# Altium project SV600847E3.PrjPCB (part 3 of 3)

## Sheet SV600847E3_6_InterfaceControl.SchDoc
size 431 x 279 mm; Date: Not shown in title block; ApprovedBy: Not shown in title block; CheckedBy: Not shown in title block; Author: Not shown in title block; CompanyName: Not shown in title block; Engineer: Not shown in title block; Organization: Not shown in title block; Address1: Not shown in title block; Address2: Not shown in title block; Address3: Not shown in title block; Address4: Not shown in title block; DocumentNumber: 6; Revision: Use project parameter SCH_Rev; SheetNumber: 6; SheetTotal: 7; PageSetup: Record=PageOptions|CenterHorizontal=True|CenterVertical=True|PrintScale=1.00|XCorrection=1.00|YCorrection=1.00|PrintKind=0|BorderSize=5000000|LeftOffset=0|BottomOffset=0|Orientation=2|PaperLength=1000|PaperWidth=1000|Scale=100|PaperSource=15|PrintQuality=600|MediaType=1|DitherType=10|PaperKind=Letter|PrintScaleMode=1
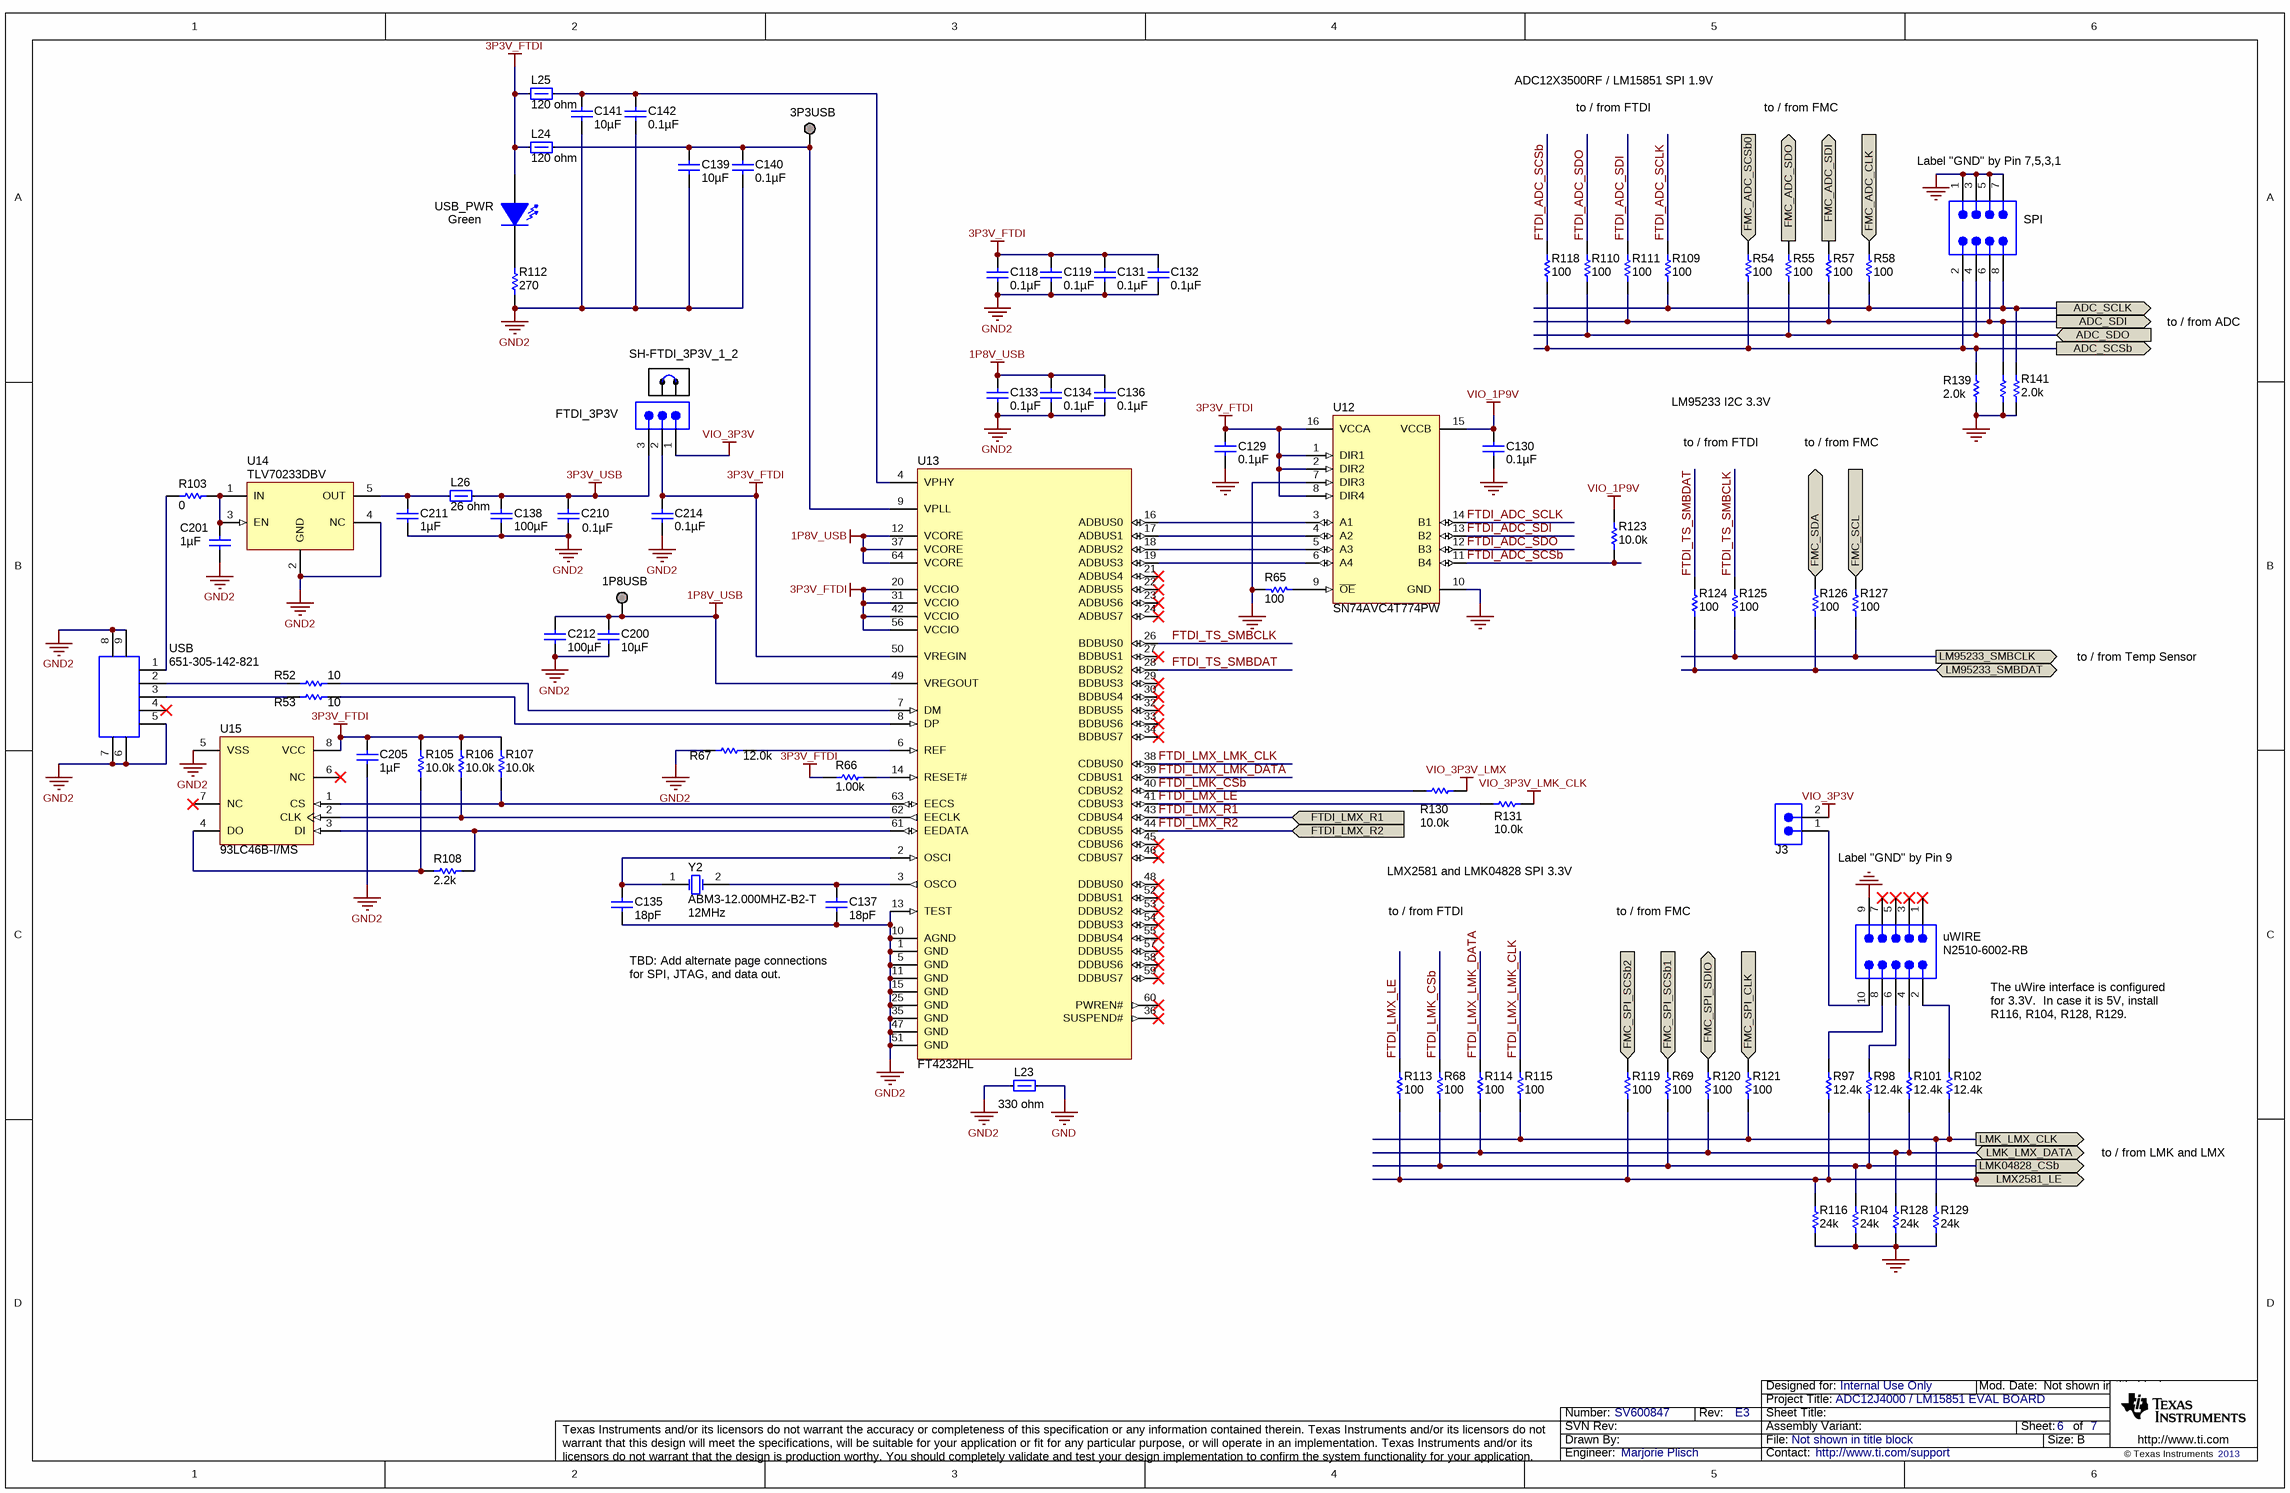
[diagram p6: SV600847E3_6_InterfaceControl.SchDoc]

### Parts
1P8USB  TESTPOINT  [TESTPOINT]  (value not drawn)  (no BOM)
3P3USB  TESTPOINT  [TESTPOINT]  (value not drawn)  (no BOM)
C118  ValueDisplayed: 0.1µF  [0201]  (hidden comment: C0603X5R0J104K)
C119  ValueDisplayed: 0.1µF  [0201]  (hidden comment: C0603X5R0J104K)
C129  ValueDisplayed: 0.1µF  [0603L]  (hidden comment: 06033C104JAT2A)
C130  ValueDisplayed: 0.1µF  [0603L]  (hidden comment: 06033C104JAT2A)
C131  ValueDisplayed: 0.1µF  [0201]  (hidden comment: C0603X5R0J104K)
C132  ValueDisplayed: 0.1µF  [0201]  (hidden comment: C0603X5R0J104K)
C133  ValueDisplayed: 0.1µF  [0201]  (hidden comment: C0603X5R0J104K)
C134  ValueDisplayed: 0.1µF  [0201]  (hidden comment: C0603X5R0J104K)
C135  ValueDisplayed: 18pF  [0402L]  (hidden comment: GRM1555C1H180JA01D)
C136  ValueDisplayed: 0.1µF  [0201]  (hidden comment: C0603X5R0J104K)
C137  ValueDisplayed: 18pF  [0402L]  (hidden comment: GRM1555C1H180JA01D)
C138  ValueDisplayed: 100µF  [1206L]  (hidden comment: GRM31CR60J107ME39L)
C139  ValueDisplayed: 10µF  [0603L]  (hidden comment: C1608X5R1A106M)
C140  ValueDisplayed: 0.1µF  [0201]  (hidden comment: C0603X5R0J104K)
C141  ValueDisplayed: 10µF  [0603L]  (hidden comment: C1608X5R1A106M)
C142  ValueDisplayed: 0.1µF  [0201]  (hidden comment: C0603X5R0J104K)
C200  ValueDisplayed: 10µF  [0603L]  (hidden comment: C1608X5R1A106M)
C201  ValueDisplayed: 1µF  [0603L]  (hidden comment: C1608X5R1C105K)
C205  ValueDisplayed: 1µF  [0603L]  (hidden comment: C1608X5R1A105K)
C210  ValueDisplayed: 0.1µF  [0603L]  (hidden comment: 0603YC104JAT2A)
C211  ValueDisplayed: 1µF  [0603L]  (hidden comment: C1608X5R1C105K)
C212  ValueDisplayed: 100µF  [1206]  (hidden comment: GRM31CR60J107ME39L)
C214  ValueDisplayed: 0.1µF  [0201]  (hidden comment: C0603X5R0J104K)
FTDI_3P3V  TSW-103-07-G-S  [TSW-103-07-G-S]  (value not drawn)
J3  TSW-102-07-G-S  [TSW-102-07-G-S]  (value not drawn)
L23  value 330 ohm  [0603]  (hidden comment: BLM18SG331TN1D)
L24  value 120 ohm  [0603]  (hidden comment: BLM18SG121TN1D)
L25  value 120 ohm  [0603L]  (hidden comment: BLM18SG121TN1D)
L26  value 26 ohm  [0603]  (hidden comment: BLM18SG260TN1D)
R52  value 10  [0603L]  (hidden comment: CRCW060310R0JNEA)
R53  value 10  [0603L]  (hidden comment: CRCW060310R0JNEA)
R54  value 100  [0603L]  (hidden comment: CRCW0603100RJNEA)
R55  value 100  [0603L]  (hidden comment: CRCW0603100RJNEA)
R57  value 100  [0603L]  (hidden comment: CRCW0603100RJNEA)
R58  value 100  [0603L]  (hidden comment: CRCW0603100RJNEA)
R65  value 100  [0603L]  (hidden comment: CRCW0603100RJNEA)
R66  value 1.00k  [0603L]  (hidden comment: CRCW06031K00FKEA)
R67  value 12.0k  [0603L]  (hidden comment: RC0603FR-0712KL)
R68  value 100  [0603L]  (hidden comment: CRCW0603100RJNEA)
R69  value 100  [0603L]  (hidden comment: CRCW0603100RJNEA)
R97  value 12.4k  [0603L]  (hidden comment: CRCW060312K4FKEA)
R98  value 12.4k  [0603L]  (hidden comment: CRCW060312K4FKEA)
R101  value 12.4k  [0603L]  (hidden comment: CRCW060312K4FKEA)
R102  value 12.4k  [0603L]  (hidden comment: CRCW060312K4FKEA)
R103  value 0  [0603L]  (hidden comment: CRCW06030000Z0EA)
R104  value 24k  [0402L]  (hidden comment: CRCW040224K0JNED)
R105  value 10.0k  [0603L]  (hidden comment: CRCW060310K0FKEA)
R106  value 10.0k  [0603L]  (hidden comment: CRCW060310K0FKEA)
R107  value 10.0k  [0603L]  (hidden comment: CRCW060310K0FKEA)
R108  value 2.2k  [0603L]  (hidden comment: RC0603JR-072K2L)
R109  value 100  [0603L]  (hidden comment: CRCW0603100RJNEA)
R110  value 100  [0603L]  (hidden comment: CRCW0603100RJNEA)
R111  value 100  [0603L]  (hidden comment: CRCW0603100RJNEA)
R112  value 270  [0603L]  (hidden comment: CRCW0603270RJNEA)
R113  value 100  [0603L]  (hidden comment: CRCW0603100RJNEA)
R114  value 100  [0603L]  (hidden comment: CRCW0603100RJNEA)
R115  value 100  [0603L]  (hidden comment: CRCW0603100RJNEA)
R116  value 24k  [0402L]  (hidden comment: CRCW040224K0JNED)
R118  value 100  [0603L]  (hidden comment: CRCW0603100RJNEA)
R119  value 100  [0603L]  (hidden comment: CRCW0603100RJNEA)
R120  value 100  [0603L]  (hidden comment: CRCW0603100RJNEA)
R121  value 100  [0603L]  (hidden comment: CRCW0603100RJNEA)
R123  value 10.0k  [0603L]  (hidden comment: CRCW060310K0FKEA)
R124  value 100  [0603L]  (hidden comment: CRCW0603100RJNEA)
R125  value 100  [0603L]  (hidden comment: CRCW0603100RJNEA)
R126  value 100  [0603L]  (hidden comment: CRCW0603100RJNEA)
R127  value 100  [0603L]  (hidden comment: CRCW0603100RJNEA)
R128  value 24k  [0402L]  (hidden comment: CRCW040224K0JNED)
R129  value 24k  [0402L]  (hidden comment: CRCW040224K0JNED)
R130  value 10.0k  [0603L]  (hidden comment: CRCW060310K0FKEA)
R131  value 10.0k  [0603L]  (hidden comment: CRCW060310K0FKEA)
R139  value 2.0k  [0603L]  (hidden comment: CRCW06032K00JNEA)
R140  CRCW06032K00JNEA  [0603L]  (value not drawn)
R141  value 2.0k  [0603L]  (hidden comment: CRCW06032K00JNEA)
SH-FTDI_3P3V_1_2  SNT-100-BK-G  [SNT-100-BK-G]  (value not drawn)
SPI  TSW-104-07-G-D  [TSW-104-07-G-D]  (value not drawn)
U12  SN74AVC4T774PW  [PW0016A_L]
U13  FT4232HL  [LQFP64_N]
U14  TLV70233DBV  [DBV0005A_N]
U15  93LC46B-I/MS  [MSOP-MS8_N]
USB  651-305-142-821  [CONN_USB-MINI-AB-651-305-142-821]
USB_PWR  value Green  [LED_LTST-C190]  (hidden comment: LTST-C190GKT)
uWIRE  N2510-6002-RB  [CONN_2510-6002]
Y2  ABM3-12.000MHZ-B2-T  Frequency: 12MHz  [XTAL_ABM3]

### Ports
ADC_SCLK (out), ADC_SCSb (out), ADC_SDI (out), ADC_SDO (in), FMC_ADC_CLK (in), FMC_ADC_SCSb0 (in), FMC_ADC_SDI (out), FMC_ADC_SDO (in), FMC_SCL (out), FMC_SDA (bidir), FMC_SPI_CLK (in), FMC_SPI_SCSb1 (in), FMC_SPI_SCSb2 (in), FMC_SPI_SDIO (bidir), FTDI_LMX_R1, FTDI_LMX_R2, LM95233_SMBCLK (out), LM95233_SMBDAT (bidir), LMK04828_CSb (out), LMK_LMX_CLK, LMK_LMX_DATA (bidir), LMX2581_LE (out)

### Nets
1P8V_USB: 1P8USB.1 C133.1 C134.1 C136.1 C200.1 C212.2 U13.12(VCORE) U13.37(VCORE) U13.49(VREGOUT) U13.64(VCORE)
3P3V_FTDI: C118.1 C119.1 C129.1 C131.1 C132.1 C205.1 C214.1 FTDI_3P3V.2 L24.1 L25.1 R66.2 R105.2 R106.2 R107.2 U12.1(DIR1) U12.2(DIR2) U12.8(DIR4) U12.16(VCCA) U13.20(VCCIO) U13.31(VCCIO) U13.42(VCCIO) U13.50(VREGIN) U13.56(VCCIO) U15.8(VCC) USB_PWR.1(A)
3P3V_USB: C138.1 C210.1 FTDI_3P3V.3 L26.2
GND: C129.2 C130.2 L23.2 R65.1 R104.1 R116.1 R128.1 R129.1 R139.1 R140.1 R141.1 SPI.1 SPI.3 SPI.5 SPI.7 U12.7(DIR3) U12.10(GND) uWIRE.9
GND2: C118.2 C119.2 C131.2 C132.2 C133.2 C134.2 C135.2 C136.2 C137.2 C138.2 C139.2 C140.2 C141.2 C142.2 C200.2 C201.2 C205.2 C210.2 C211.2 C212.1 C214.2 L23.1 R67.1 R112.1 U13.1(GND) U13.5(GND) U13.10(AGND) U13.11(GND) U13.13(TEST) U13.15(GND) U13.25(GND) U13.35(GND) U13.47(GND) U13.51(GND) U14.2(GND) U14.4(NC) U15.5(VSS) USB.5 USB.6 USB.7 USB.8 USB.9
VIO_1P9V: C130.1 R123.2 U12.15(VCCB)
VIO_3P3V: FTDI_3P3V.1 J3.2
VIO_3P3V_LMK_CLK: R131.1
VIO_3P3V_LMX: R130.1
FTDI_ADC_SCLK: R109.2 U12.14(B1)
FTDI_ADC_SCSb: R118.2 R123.1 U12.11(B4)
FTDI_ADC_SDI: R111.2 U12.13(B2)
FTDI_ADC_SDO: R110.2 U12.12(B3)
FTDI_LMK_CSb: R68.2 R130.2 U13.40(CDBUS2)
FTDI_LMX_LE: R113.2 R131.2 U13.41(CDBUS3)
FTDI_LMX_LMK_CLK: R115.2 U13.38(CDBUS0)
FTDI_LMX_LMK_DATA: R114.2 U13.39(CDBUS1)
FTDI_LMX_R1: U13.43(CDBUS4) ; port FTDI_LMX_R1
FTDI_LMX_R2: U13.44(CDBUS5) ; port FTDI_LMX_R2
FTDI_TS_SMBCLK: R125.2 U13.26(BDBUS0)
FTDI_TS_SMBDAT: R124.2 U13.28(BDBUS2)
LMK04828_CSb: R68.1 R69.1 R98.1 R104.2 ; port LMK04828_CSb
LMK_LMX_CLK: R102.1 R115.1 R121.1 R129.2 ; port LMK_LMX_CLK
LMK_LMX_DATA: R101.1 R114.1 R120.1 R128.2 ; port LMK_LMX_DATA
LMX2581_LE: R97.1 R113.1 R116.2 R119.1 ; port LMX2581_LE
Net3P3USB_1: 3P3USB.1 C139.1 C140.1 L24.2 U13.9(VPLL)
NetC135_1: C135.1 U13.2(OSCI) Y2.1(OSC1)
NetC137_1: C137.1 U13.3(OSCO) Y2.2(OSC2)
NetC141_1: C141.1 C142.1 L25.2 U13.4(VPHY)
NetC201_1: C201.1 R103.2 U14.1(IN) U14.3(EN)
NetC211_1: C211.1 L26.1 U14.5(OUT)
NetFMC_RX1_C30: R127.2 ; port FMC_SCL
NetFMC_RX1_C31: R126.2 ; port FMC_SDA
NetFMC_RX1_G30: R121.2 ; port FMC_SPI_CLK
NetFMC_RX1_G33: R69.2 ; port FMC_SPI_SCSb1
NetFMC_RX1_G34: R119.2 ; port FMC_SPI_SCSb2
NetFMC_RX1_G36: R57.2 ; port FMC_ADC_SDI
NetFMC_RX1_G37: R55.2 ; port FMC_ADC_SDO
NetFMC_RX1_H34: R120.2 ; port FMC_SPI_SDIO
NetFMC_RX1_H37: R58.2 ; port FMC_ADC_CLK
NetFMC_RX1_H38: R54.2 ; port FMC_ADC_SCSb0
NetJ3_1: J3.1 uWIRE.10
NetR31_1: R124.1 R126.1 ; port LM95233_SMBDAT
NetR32_1: R125.1 R127.1 ; port LM95233_SMBCLK
NetR52_1: R52.1 USB.2
NetR52_2: R52.2 U13.7(DM)
NetR53_1: R53.1 USB.3
NetR53_2: R53.2 U13.8(DP)
NetR54_1: R54.1 R118.1 R139.2 SPI.2 ; port ADC_SCSb
NetR55_1: R55.1 R110.1 SPI.4 ; port ADC_SDO
NetR57_1: R57.1 R111.1 R140.2 SPI.6 ; port ADC_SDI
NetR58_1: R58.1 R109.1 R141.2 SPI.8 ; port ADC_SCLK
NetR65_2: R65.2 U12.9(~{OE})
NetR66_1: R66.1 U13.14(RESET#)
NetR67_2: R67.2 U13.6(REF)
NetR97_2: R97.2 uWIRE.8
NetR98_2: R98.2 uWIRE.6
NetR101_2: R101.2 uWIRE.4
NetR102_2: R102.2 uWIRE.2
NetR103_1: R103.1 USB.1
NetR105_1: R105.1 R108.2 U15.4(DO)
NetR106_1: R106.1 U13.62(EECLK) U15.2(CLK)
NetR107_1: R107.1 U13.63(EECS) U15.1(CS)
NetR108_1: R108.1 U13.61(EEDATA) U15.3(DI)
NetR112_2: R112.2 USB_PWR.2(K)
NetU12_3: U12.3(A1) U13.16(ADBUS0)
NetU12_4: U12.4(A2) U13.17(ADBUS1)
NetU12_5: U12.5(A3) U13.18(ADBUS2)
NetU12_6: U12.6(A4) U13.19(ADBUS3)

Not connected (* = marked no-connect by the designer): U13 21(ADBUS4)* 22(ADBUS5)* 23(ADBUS6)* 24(ADBUS7)* 27(BDBUS1)* 29(BDBUS3)* 30(BDBUS4)* 32(BDBUS5)* 33(BDBUS6)* 34(BDBUS7)* 36(SUSPEND#)* 45(CDBUS6)* 46(CDBUS7)* 48(DDBUS0)* 52(DDBUS1)* 53(DDBUS2)* 54(DDBUS3)* 55(DDBUS4)* 57(DDBUS5)* 58(DDBUS6)* 59(DDBUS7)* 60(PWREN#)*; U15 6(NC)* 7(NC)*; USB 4*; uWIRE 1* 3* 5* 7*

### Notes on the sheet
- ADC12X3500RF / LM15851 SPI 1.9V
- to / from FTDI
- to / from FMC
- (near SPI) Label "GND" by Pin 7,5,3,1
- to / from ADC
- LM95233 I2C 3.3V
- to / from Temp Sensor
- LMX2581 and LMK04828 SPI 3.3V
- Label "GND" by Pin 9
- TBD: Add alternate page connections for SPI, JTAG, and data out.
- The uWire interface is configured for 3.3V.  In case it is 5V, install R116, R104, R128, R129.
- to / from LMK and LMX

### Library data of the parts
1P8USB 3P3USB = TESTPOINT: TEST POINT.  No entry in BOM.
C118 C119 C131-C134 C136 C140 C142 C214 = Capacitor: CAP, CERM, 0.1uF, 6.3V, X5R, 10%, 0201; Manufacturer: TDK; Polarized: N; U/M: EA
C129 C130 = 06033C104JAT2A: CAP, CERM, 0.1uF, 25V, +/-5%, X7R, 0603; Manufacturer: AVX; Polarized: N; CompType: Capacitor; U/M: EA; Cap_F: 0.0000001; Tolerance_%: 5; ESR_Ohm: 0.05; Value1: 0.05 ohm; VDC_V: 25; TaMin_C: -55; TaMax_C: 125; Cap_Case: 0603
C135 C137 = GRM1555C1H180JA01D: CAP, CERM, 18pF, 50V, +/-5%, C0G/NP0, 0402; Manufacturer: MuRata; Polarized: N; CompType: Capacitor; U/M: EA; Cap_F: 0.000000000018; Tolerance_%: 5; Value1: Unknown; VDC_V: 50; TaMin_C: -55; TaMax_C: 125; Cap_Case: 0402
C138 = GRM31CR60J107ME39L: CAP, CERM, 100uF, 6.3V, +/-20%, X5R, 1206; Manufacturer: MuRata; Polarized: N; CompType: Capacitor; U/M: EA; Cap_F: 0.0001; Tolerance_%: 20; ESR_Ohm: 0.003; Value1: 0.003 ohm; VDC_V: 6.3; TaMin_C: -55; TaMax_C: 85; Cap_Case: 1206
C139 C141 C200 = C1608X5R1A106M: CAP, CERM, 10uF, 10V, +/-10%, C0G/NP0, 0603; Manufacturer: TDK; Polarized: N; CompType: Capacitor; U/M: EA; Cap_F: 0.00001; Tolerance_%: 10; ESR_Ohm: 0.0078; Value1: 0.0078 ohm; IRMS_A: 1.85; TaMin_C: -55; TaMax_C: 85; Cap_Case: 0603
C201 C211 = C1608X5R1C105K: CAP, CERM, 1uF, 16V, +/-10%, X5R, 0603; Manufacturer: TDK; Polarized: N; CompType: Capacitor; U/M: EA; Cap_F: 0.000001; Tolerance_%: 10; ESR_Ohm: 0.0057; Value1: 0.0057 ohm; VDC_V: 16; TaMin_C: -55; TaMax_C: 85; Cap_Case: 0603
C205 = C1608X5R1A105K: CAP, CERM, 1uF, 10V, +/-10%, X5R, 0603; Manufacturer: TDK; Polarized: N; CompType: Capacitor; U/M: EA; Cap_F: 0.000001; Tolerance_%: 10; ESR_Ohm: 0.0057; Value1: 0.0057 ohm; TaMin_C: -55; TaMax_C: 85; Cap_Case: 0603
C210 = 0603YC104JAT2A: CAP, CERM, 0.1uF, 16V, +/-5%, X7R, 0603; Manufacturer: AVX; Polarized: N; CompType: Capacitor; U/M: EA; Cap_F: 0.0000001; Tolerance_%: 5; ESR_Ohm: 0.039; Value1: 0.039 ohm; VDC_V: 16; TaMin_C: -55; TaMax_C: 125; Cap_Case: 0603
C212 = GRM31CR60J107ME39L: CAP, CERM, 100uF, 6.3V, +/-20%, X5R, 1206; Manufacturer: MuRata; Polarized: N; CompType: Capacitor; U/M: EA; Cap_F: 0.0001; Tolerance_%: 20; ESR_Ohm: 0.003; Value1: 0.003 ohm; VDC_V: 6.3; TaMin_C: -55; TaMax_C: 85
FTDI_3P3V = TSW-103-07-G-S: Header, TH, 100mil, 3x1, Gold plated, 230 mil above insulator; Manufacturer: Samtec, Inc.; Alternate Manufacturer: Any; Alternate PartNumber: Equivalent; U/M: EA
J3 = TSW-102-07-G-S: Header, TH, 100mil, 2x1, Gold plated, 230 mil above insulator; Manufacturer: Samtec, Inc.; U/M: EA
L23 = BLM18SG331TN1D: 1.5A Ferrite Bead, 330 ohm @ 100MHz, SMD; Manufacturer: MuRata; Imax_A: 1.5; DCR_ohm: 0.07; Value1: 0.07 ohm; ZTyp@100MHz_Ohm: 330; U/M: EA
L24 L25 = BLM18SG121TN1D: 3A Ferrite Bead, 120 ohm @ 100MHz, SMD; Manufacturer: MuRata; Imax_A: 3; DCR_ohm: 0.025; Value1: 0.025 ohm; ZTyp@100MHz_Ohm: 120; U/M: EA
L26 = BLM18SG260TN1D: 6A Ferrite Bead, 26 ohm @ 100MHz, SMD; Manufacturer: MuRata; Imax_A: 6; DCR_ohm: 0.007; Value1: 0.007 ohm; ZTyp@100MHz_Ohm: 26; U/M: EA
R52 R53 = CRCW060310R0JNEA: RES, 10 ohm, 5%, 0.1W, 0603; Manufacturer: Vishay-Dale; CompType: Resistor; Value_Code: 10R0; Tolerance_%: 5; Power_W: 0.1; VDC_V: 75; TempCo: 200 ppm/C; EIA_Code: E24; U/M: EA
R54 R55 R57 R58 R65 R68 R69 R109-R111 R113-R115 R118-R121 R124-R127 = CRCW0603100RJNEA: RES, 100 ohm, 5%, 0.1W, 0603; Manufacturer: Vishay-Dale; CompType: Resistor; Value_Code: 100R; Tolerance_%: 5; Power_W: 0.1; VDC_V: 75; TempCo: 200 ppm/C; EIA_Code: E24; U/M: EA
R66 = CRCW06031K00FKEA: RES, 1.00k ohm, 1%, 0.1W, 0603; Manufacturer: Vishay-Dale; CompType: Resistor; Tolerance_%: 1; VDC_V: 75; Power_W: 0.1; Res_ohm: 1000; TempCo_ppm/C: 100; Value_Code: 1k00; EIA_Code: E96; U/M: EA
R67 = RC0603FR-0712KL: RES, 12.0k ohm, 1%, 0.1W, 0603; Manufacturer: Yageo America; CompType: Resistor; Res_ohm: 12000; Value_Code: 12k0; Tolerance_%: 1; Power_W: 0.1; VDC_V: 150; TempCo: 200 ppm/C; U/M: EA
R97 R98 R101 R102 = CRCW060312K4FKEA: RES, 12.4k ohm, 1%, 0.1W, 0603; Manufacturer: Vishay-Dale; CompType: Resistor; Res_ohm: 12400; Value_Code: 12k4; Tolerance_%: 1; Power_W: 0.1; VDC_V: 75; TempCo: 100 ppm/C; EIA_Code: E96; U/M: EA
R103 = CRCW06030000Z0EA: RES, 0 ohm, 5%, 0.1W, 0603; Manufacturer: Vishay-Dale; CompType: Resistor; Value_Code: 0000; Tolerance_%: 5; Power_W: 0.1; VDC_V: 75; TempCo: 200 ppm/C; EIA_Code: E24; U/M: EA
R104 R116 R128 R129 = CRCW040224K0JNED: RES, 24k ohm, 5%, 0.063W, 0402; Manufacturer: Vishay-Dale; CompType: Resistor; Res_ohm: 24000; Value_Code: 24k0; Tolerance_%: 5; Power_W: 0.063; VDC_V: 50; TempCo: 200 ppm/C; EIA_Code: E24; U/M: EA
R105-R107 R123 R130 R131 = CRCW060310K0FKEA: RES, 10.0k ohm, 1%, 0.1W, 0603; Manufacturer: Vishay-Dale; CompType: Resistor; Res_ohm: 10000; Value_Code: 10k0; Tolerance_%: 1; Power_W: 0.1; VDC_V: 75; TempCo: 100 ppm/C; EIA_Code: E96; U/M: EA
R108 = RC0603JR-072K2L: RES, 2.2k ohm, 5%, 0.1W, 0603; Manufacturer: Yageo America; CompType: Resistor; Res_ohm: 2200; Value_Code: 2k20; Tolerance_%: 5; Power_W: 0.1; VDC_V: 50; TempCo: 100 ppm/C; EIA_Code: E24; U/M: EA
R112 = CRCW0603270RJNEA: RES, 270 ohm, 5%, 0.1W, 0603; Manufacturer: Vishay-Dale; Alternate Manufacturer: Any; Alternate PartNumber: Equivalent; CompType: Resistor; Value_Code: 270R; Tolerance_%: 5; Power_W: 0.1; VDC_V: 75; TempCo: 200 ppm/C; EIA_Code: E24; U/M: EA
R139-R141 = CRCW06032K00JNEA: RES, 2.0k ohm, 5%, 0.1W, 0603; Manufacturer: Vishay-Dale; CompType: Resistor; Res_ohm: 2000; Value_Code: 2k00; Tolerance_%: 5; Power_W: 0.1; VDC_V: 75; TempCo: 200 ppm/C; EIA_Code: E24; U/M: EA
SH-FTDI_3P3V_1_2 = SNT-100-BK-G: Shunt, 100mil, Gold plated, Black; Manufacturer: Samtec, Inc.; Alternate Manufacturer: 3M; Alternate PartNumber: 969102-0000-DA; Value: 1x2; Note: You can "mate" this to a header by matching the designator.  i.e. use SH-J3 for header J3
SPI = TSW-104-07-G-D: Header, TH, 100mil, 4x2, Gold plated, 230 mil above insulator; Manufacturer: Samtec, Inc.; U/M: EA
U12 = SN74AVC4T774PW: 4-BIT DUAL-SUPPLY BUS TRANSCEIVER WITH CONFIGURABLE VOLTAGE TRANSLATION AND 3-STATE OUTPUTS, PW0016A; Alternate Manufacturer: None; Manufacturer: Texas Instruments; SymbolCreator: a0411947; CompType: IC; U/M: EA
U13 = FT4232HL: Quad High Speed USB to Multipurpose UART/MPSSE IC; Manufacturer: FTDI; SymbolCreator: a0411947
U14 = TLV70233DBV: 300-mA, Low-IQ, Low-Dropout Regulator, DBV0005A; Alternate Manufacturer: None; Manufacturer: Texas Instruments; SymbolCreator: a0411947; CompType: IC; U/M: EA
U15 = 93LC46B-I/MS: 1K, 64x16-bit, 2.5V Microwire Serial EEPROM, 8-Pin MSOP, Industrial Temperature
USB = 651-305-142-821: MINI USB 2.0 SMT TYPE AB 5 CONTACTS R/A, SMD; Manufacturer: Wurth Elektronik eiSos; SymbolCreator: a0799628; CompType: Connector; U/M: EA
USB_PWR = LTST-C190GKT: LED, Green, SMD; Manufacturer: Lite-On; Vf_V: 2.1; Value2: 2.1V; Io_A: 0.02; Power_TotalModule: 0.1; Value1: 0.1W; U/M: EA
uWIRE = N2510-6002-RB: Connector, 100mil Shrouded, 5x2, High-Temperature, Gold, TH; Manufacturer: 3M; SymbolCreator: a0412235; U/M: EA
Y2 = ABM3-12.000MHZ-B2-T: Crystal, 12Mhz, 18pF, SMD; Manufacturer: Abracon Corportation; SymbolCreator: a0412235; U/M: EA; TaMin_C: -20; TaMax_C: 70; Frequency Stability: ±50ppm

## Sheet SV600847E3_7_Hardware.SchDoc
size 431 x 279 mm; Date: Not shown in title block; ApprovedBy: Not shown in title block; CheckedBy: Not shown in title block; Author: Not shown in title block; CompanyName: Not shown in title block; Engineer: Not shown in title block; Organization: Not shown in title block; Address1: Not shown in title block; Address2: Not shown in title block; Address3: Not shown in title block; Address4: Not shown in title block; DocumentNumber: 7; Revision: Use project parameter SCH_Rev; SheetNumber: 7; SheetTotal: 7; PageSetup: Record=PageOptions|CenterHorizontal=True|CenterVertical=True|PrintScale=1.00|XCorrection=1.00|YCorrection=1.00|PrintKind=0|BorderSize=5000000|LeftOffset=0|BottomOffset=0|Orientation=2|PaperLength=1000|PaperWidth=1000|Scale=100|PaperSource=15|PrintQuality=600|MediaType=1|DitherType=10|PaperKind=Letter|PrintScaleMode=1
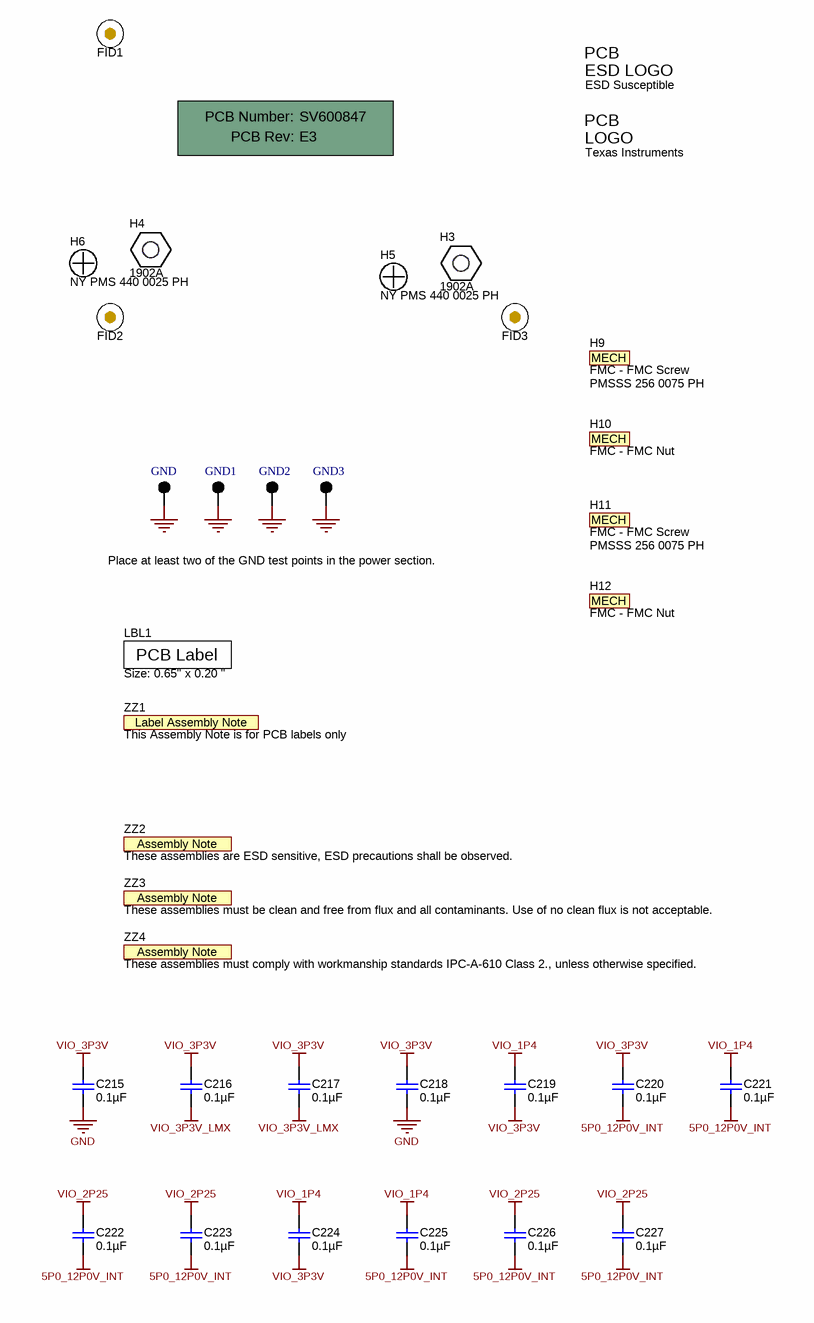
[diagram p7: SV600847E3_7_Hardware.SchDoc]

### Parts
!PCB  Printed Circuit Board  (value not drawn)  (mechanical)
C215  ValueDisplayed: 0.1µF  [0402L]  (hidden comment: GRM155R71A104KA01D)
C216  ValueDisplayed: 0.1µF  [0402L]  (hidden comment: GRM155R71A104KA01D)
C217  ValueDisplayed: 0.1µF  [0402L]  (hidden comment: GRM155R71A104KA01D)
C218  ValueDisplayed: 0.1µF  [0402L]  (hidden comment: GRM155R71A104KA01D)
C219  ValueDisplayed: 0.1µF  [0402L]  (hidden comment: GRM155R71A104KA01D)
C220  ValueDisplayed: 0.1µF  [0402L]  (hidden comment: GRM155R71A104KA01D)
C221  ValueDisplayed: 0.1µF  [0402L]  (hidden comment: GRM155R71A104KA01D)
C222  ValueDisplayed: 0.1µF  [0402L]  (hidden comment: GRM155R71A104KA01D)
C223  ValueDisplayed: 0.1µF  [0402L]  (hidden comment: GRM155R71A104KA01D)
C224  ValueDisplayed: 0.1µF  [0402L]  (hidden comment: GRM155R71A104KA01D)
C225  ValueDisplayed: 0.1µF  [0402L]  (hidden comment: GRM155R71A104KA01D)
C226  ValueDisplayed: 0.1µF  [0402L]  (hidden comment: GRM155R71A104KA01D)
C227  ValueDisplayed: 0.1µF  [0402L]  (hidden comment: GRM155R71A104KA01D)
FID1  Fiducial  [Fiducial10-30]  (value not drawn)
FID2  Fiducial  [Fiducial10-30]  (value not drawn)
FID3  Fiducial  [Fiducial10-30]  (value not drawn)
GND  5011  [Keystone5011]  (value not drawn)
GND1  5011  [Keystone5011]  (value not drawn)
GND2  5011  [Keystone5011]  (value not drawn)
GND3  5011  [Keystone5011]  (value not drawn)
H3  1902A  [Keystone_1902C]
H4  1902A  [Keystone_1902C]
H5  NY PMS 440 0025 PH  [NY PMS 440 0025 PH]
H6  NY PMS 440 0025 PH  [NY PMS 440 0025 PH]
H9  FMC - FMC Screw  PartNumber: PMSSS 256 0075 PH  (mechanical)
H10  FMC - FMC Nut  (mechanical)
H11  FMC - FMC Screw  PartNumber: PMSSS 256 0075 PH  (mechanical)
H12  FMC - FMC Nut  (mechanical)
LBL1  Size: 0.65" x 0.20 "  [Label_650x200]
Logo1  ESD Susceptible  [ESD_Overlay_Small]  (no BOM)
Logo2  Texas Instruments  [TI_Symbol_Overlay_Small]  (no BOM)
ZZ1  This Assembly Note is for PCB labels only  [AssemblyNoteLabel]  (no BOM)
ZZ2  These assemblies are ESD sensitive, ESD precautions shall be observed.  [AssemblyNote]  (no BOM)
ZZ3  These assemblies must be clean and free from flux and all contaminants. Use of no clean flux is not acceptable.  [AssemblyNote]  (no BOM)
ZZ4  These assemblies must comply with workmanship standards IPC-A-610 Class 2., unless otherwise specified.  [AssemblyNote]  (no BOM)

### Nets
5P0_12P0V_INT: C220.2 C221.2 C222.2 C223.2 C225.2 C226.2 C227.2
GND: C215.2 C218.2 GND.1 GND1.1 GND2.1 GND3.1
VIO_1P4: C219.1 C221.1 C224.1 C225.1
VIO_2P25: C222.1 C223.1 C226.1 C227.1
VIO_3P3V: C215.1 C216.1 C217.1 C218.1 C219.2 C220.1 C224.2
VIO_3P3V_LMX: C216.2 C217.2

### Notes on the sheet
- Place at least two of the GND test points in the power section.

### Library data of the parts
!PCB = PCB: Manufacturer: Any; PartNumber: SV600847; SymbolCreator: a0412235
C215-C227 = GRM155R71A104KA01D: CAP, CERM, 0.1uF, 10V, +/-10%, X7R, 0402; Manufacturer: MuRata; Polarized: N; CompType: Capacitor; U/M: EA; Cap_F: 0.0000001; Tolerance_%: 10; TaMin_C: -55; TaMax_C: 125; Cap_Case: 0402
FID1-FID3 = Fiducial: Fiducial mark.  There is nothing to buy or mount.; SymbolCreator: codlsc
GND GND1-GND3 = 5011: Test Point, TH, Multipurpose, Black; Manufacturer: Keystone Electronics; CompType: Test Point Loop
H3 H4 = 1902C: Standoff, Hex, 0.25"L #4-40 Nylon; Manufacturer: Keystone; CompType: Hardware; U/M: EA
H5 H6 = NY PMS 440 0025 PH: Machine Screw, Round, #4-40 x 1/4, Nylon, Philips panhead; Manufacturer: B&F Fastener Supply; CompType: Hardware; SymbolCreator: codlsc; U/M: EA
H9 H11 = MechPart: Will add component to BOM.  Useful for cables, nuts, etc. not in libraries; Manufacturer: B&F Fastner Supply; SymbolCreator: codlsc; CompType: Mechanical; U/M: EA
H10 H12 = MechPart: Will add component to BOM.  Useful for cables, nuts, etc. not in libraries; Manufacturer: B & F Fastener Supply; PartNumber: HNSS256; SymbolCreator: codlsc; CompType: Mechanical; U/M: EA
LBL1 = THT-14-423-10: Thermal Transfer Printable Labels, 0.650" W x 0.200" H - 10,000 per roll; Manufacturer: Brady; SymbolCreator: a0412235; CompType: Label
Logo1 = ESD_Susceptible: ESD Susceptible Symbol; SymbolCreator: codlsc
Logo2 = TI_Logo: Texas Instrument Corporate Signature; SymbolCreator: codlsc
ZZ1 = AssemblyNoteLabel: SymbolCreator: a0412235
ZZ2-ZZ4 = AssemblyNote: SymbolCreator: codlsc

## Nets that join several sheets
5P0_12P0V_INT: SV600847E3_5_Power (16 pins), SV600847E3_7_Hardware (7 pins)
12P0V_RX: SV600847E3_2_FMC (FMC_RX1.C35 FMC_RX1.C37), SV600847E3_5_Power (EXT5V_FMC12V.3)
GND: SV600847E3_1_ADC_IO (101 pins), SV600847E3_2_FMC (164 pins), SV600847E3_3_LMX2581 (33 pins), SV600847E3_4_LMK04828 (31 pins), SV600847E3_5_Power (80 pins), SV600847E3_6_InterfaceControl (18 pins), SV600847E3_7_Hardware (6 pins)
VIO_1P2VA: SV600847E3_1_ADC_IO (18 pins), SV600847E3_5_Power (C177.1 C188.1 L15.2)
VIO_1P2VD: SV600847E3_1_ADC_IO (28 pins), SV600847E3_5_Power (C189.1 C197.1 L16.2)
VIO_1P4: SV600847E3_5_Power (5 pins), SV600847E3_7_Hardware (C219.1 C221.1 C224.1 C225.1)
VIO_1P9V: SV600847E3_1_ADC_IO (20 pins), SV600847E3_5_Power (6 pins), SV600847E3_6_InterfaceControl (C130.1 R123.2 U12.15)
VIO_2P25: SV600847E3_5_Power (5 pins), SV600847E3_7_Hardware (C222.1 C223.1 C226.1 C227.1)
VIO_3P3V: SV600847E3_1_ADC_IO (15 pins), SV600847E3_5_Power (C153.1 C163.1 L9.2), SV600847E3_6_InterfaceControl (FTDI_3P3V.1 J3.2), SV600847E3_7_Hardware (7 pins)
VIO_3P3V_LMK_CLK: SV600847E3_4_LMK04828 (6 pins), SV600847E3_5_Power (C116.1 C171.1 L13.2), SV600847E3_6_InterfaceControl (R131.1)
VIO_3P3V_LMK_PLL: SV600847E3_4_LMK04828 (16 pins), SV600847E3_5_Power (C164.1 C165.1 L10.2)
VIO_3P3V_LMX: SV600847E3_3_LMX2581 (25 pins), SV600847E3_5_Power (C144.1 C152.1 L6.2), SV600847E3_6_InterfaceControl (R130.1), SV600847E3_7_Hardware (C216.2 C217.2)
D0_N: SV600847E3_1_ADC_IO (C9.1), SV600847E3_2_FMC (FMC_RX1.C6)
D0_P: SV600847E3_1_ADC_IO (C7.1), SV600847E3_2_FMC (FMC_RX1.C7)
D1_N: SV600847E3_1_ADC_IO (C12.1), SV600847E3_2_FMC (FMC_RX1.A2)
D1_P: SV600847E3_1_ADC_IO (C10.1), SV600847E3_2_FMC (FMC_RX1.A3)
D2_N: SV600847E3_1_ADC_IO (C14.1), SV600847E3_2_FMC (FMC_RX1.A6)
D2_P: SV600847E3_1_ADC_IO (C13.1), SV600847E3_2_FMC (FMC_RX1.A7)
D3_N: SV600847E3_1_ADC_IO (C17.1), SV600847E3_2_FMC (FMC_RX1.A10)
D3_P: SV600847E3_1_ADC_IO (C15.1), SV600847E3_2_FMC (FMC_RX1.A11)
D4_N: SV600847E3_1_ADC_IO (C21.1), SV600847E3_2_FMC (FMC_RX1.A14)
D4_P: SV600847E3_1_ADC_IO (C20.1), SV600847E3_2_FMC (FMC_RX1.A15)
D5_N: SV600847E3_1_ADC_IO (C23.1), SV600847E3_2_FMC (FMC_RX1.A18)
D5_P: SV600847E3_1_ADC_IO (C22.1), SV600847E3_2_FMC (FMC_RX1.A19)
D6_N: SV600847E3_1_ADC_IO (C28.1), SV600847E3_2_FMC (FMC_RX1.B16)
D6_P: SV600847E3_1_ADC_IO (C26.1), SV600847E3_2_FMC (FMC_RX1.B17)
D7_N: SV600847E3_1_ADC_IO (C31.1), SV600847E3_2_FMC (FMC_RX1.B12)
D7_P: SV600847E3_1_ADC_IO (C29.1), SV600847E3_2_FMC (FMC_RX1.B13)
DEVCLKARX_N: SV600847E3_2_FMC (FMC_RX1.D5), SV600847E3_4_LMK04828 (R60.2)
DEVCLKARX_P: SV600847E3_2_FMC (FMC_RX1.D4), SV600847E3_4_LMK04828 (R59.2)
DEVCLKBRX_N: SV600847E3_2_FMC (FMC_RX1.G7), SV600847E3_4_LMK04828 (R63.2)
DEVCLKBRX_P: SV600847E3_2_FMC (FMC_RX1.G6), SV600847E3_4_LMK04828 (R64.2)
FTDI_LMX_R1: SV600847E3_3_LMX2581 (R143.2), SV600847E3_6_InterfaceControl (U13.43)
FTDI_LMX_R2: SV600847E3_3_LMX2581 (R142.2), SV600847E3_6_InterfaceControl (U13.44)
LM15851_OR_T0: SV600847E3_1_ADC_IO (D2.2 OR.3 U2.25), SV600847E3_2_FMC (FMC_RX1.G27)
LM15851_OR_T1: SV600847E3_1_ADC_IO (D4.2 OR.1 U2.26), SV600847E3_2_FMC (FMC_RX1.D26)
LMK04828_CSb: SV600847E3_4_LMK04828 (U6.18), SV600847E3_6_InterfaceControl (R68.1 R69.1 R98.1 R104.2)
LMK04828_RESET: SV600847E3_2_FMC (FMC_RX1.J16), SV600847E3_4_LMK04828 (R122.2 U6.5)
LMK04828_SYNC: SV600847E3_2_FMC (FMC_RX1.J15), SV600847E3_4_LMK04828 (R47.1 U6.6)
LMK_LMX_CLK: SV600847E3_3_LMX2581 (U4.1), SV600847E3_4_LMK04828 (U6.19), SV600847E3_6_InterfaceControl (R102.1 R115.1 R121.1 R129.2)
LMK_LMX_DATA: SV600847E3_3_LMX2581 (U4.2), SV600847E3_4_LMK04828 (U6.20), SV600847E3_6_InterfaceControl (R101.1 R114.1 R120.1 R128.2)
LMX2581_CE: SV600847E3_2_FMC (FMC_RX1.H22), SV600847E3_3_LMX2581 (R117.1 U4.4)
LMX2581_LE: SV600847E3_3_LMX2581 (U4.3), SV600847E3_6_InterfaceControl (R97.1 R113.1 R116.2 R119.1)
LMX_OutA_N: SV600847E3_3_LMX2581 (C101.1), SV600847E3_4_LMK04828 (C112.2)
LMX_OutA_P: SV600847E3_3_LMX2581 (C96.2), SV600847E3_4_LMK04828 (C113.2)
LMX_OutB_N: SV600847E3_1_ADC_IO (C33.2), SV600847E3_3_LMX2581 (C100.1)
LMX_OutB_P: SV600847E3_1_ADC_IO (C32.2), SV600847E3_3_LMX2581 (C97.2)
NetFMC_RX1_C30: SV600847E3_2_FMC (FMC_RX1.C30 J1.2 U16.6), SV600847E3_6_InterfaceControl (R127.2)
NetFMC_RX1_C31: SV600847E3_2_FMC (FMC_RX1.C31 J1.1 U16.5), SV600847E3_6_InterfaceControl (R126.2)
NetFMC_RX1_E12: SV600847E3_1_ADC_IO (R136.2), SV600847E3_2_FMC (FMC_RX1.E12)
NetFMC_RX1_E13: SV600847E3_1_ADC_IO (R137.2), SV600847E3_2_FMC (FMC_RX1.E13)
NetFMC_RX1_E36: SV600847E3_1_ADC_IO (R138.2), SV600847E3_2_FMC (FMC_RX1.E36)
NetFMC_RX1_G30: SV600847E3_2_FMC (FMC_RX1.G30), SV600847E3_6_InterfaceControl (R121.2)
NetFMC_RX1_G33: SV600847E3_2_FMC (FMC_RX1.G33), SV600847E3_6_InterfaceControl (R69.2)
NetFMC_RX1_G34: SV600847E3_2_FMC (FMC_RX1.G34), SV600847E3_6_InterfaceControl (R119.2)
NetFMC_RX1_G36: SV600847E3_2_FMC (FMC_RX1.G36), SV600847E3_6_InterfaceControl (R57.2)
NetFMC_RX1_G37: SV600847E3_2_FMC (FMC_RX1.G37), SV600847E3_6_InterfaceControl (R55.2)
NetFMC_RX1_H23: SV600847E3_2_FMC (FMC_RX1.H23), SV600847E3_3_LMX2581 (R46.1 U4.26)
NetFMC_RX1_H34: SV600847E3_2_FMC (FMC_RX1.H34), SV600847E3_6_InterfaceControl (R120.2)
NetFMC_RX1_H37: SV600847E3_2_FMC (FMC_RX1.H37), SV600847E3_6_InterfaceControl (R58.2)
NetFMC_RX1_H38: SV600847E3_2_FMC (FMC_RX1.H38), SV600847E3_6_InterfaceControl (R54.2)
NetR31_1: SV600847E3_1_ADC_IO (R31.1 U3.12), SV600847E3_6_InterfaceControl (R124.1 R126.1)
NetR32_1: SV600847E3_1_ADC_IO (R32.1 U3.13), SV600847E3_6_InterfaceControl (R125.1 R127.1)
NetR54_1: SV600847E3_1_ADC_IO (U2.59), SV600847E3_6_InterfaceControl (R54.1 R118.1 R139.2 SPI.2)
NetR55_1: SV600847E3_1_ADC_IO (U2.56), SV600847E3_6_InterfaceControl (R55.1 R110.1 SPI.4)
NetR57_1: SV600847E3_1_ADC_IO (U2.57), SV600847E3_6_InterfaceControl (R57.1 R111.1 R140.2 SPI.6)
NetR58_1: SV600847E3_1_ADC_IO (U2.58), SV600847E3_6_InterfaceControl (R58.1 R109.1 R141.2 SPI.8)
SYNC_N: SV600847E3_1_ADC_IO (R20.2), SV600847E3_2_FMC (FMC_RX1.G13)
SYNC_P: SV600847E3_1_ADC_IO (R19.2), SV600847E3_2_FMC (FMC_RX1.G12)
SYNC_SE: SV600847E3_1_ADC_IO (R134.1), SV600847E3_2_FMC (FMC_RX1.H31)
SYSREFRX_N: SV600847E3_2_FMC (FMC_RX1.G10), SV600847E3_4_LMK04828 (R61.2)
SYSREFRX_P: SV600847E3_2_FMC (FMC_RX1.G9), SV600847E3_4_LMK04828 (R62.2)
SYSREFTX_N: SV600847E3_1_ADC_IO (C37.2), SV600847E3_4_LMK04828 (R43.2)
SYSREFTX_P: SV600847E3_1_ADC_IO (C35.2), SV600847E3_4_LMK04828 (R44.2)

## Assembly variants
002: not fitted C1 C6 C30 C36 C74 C114 C123 R7 R8 R9 R18 R21 R22 R23 R25 R26 R34 R40 R42 R54 R55 R57 R58 R69 R73 R75 R83 R84 R90 R92 R95 R99 R104 R116 R119 R120 R121 R126 R127 R128 R129 R139 R140 R141 R142
001: not fitted C1 C6 C30 C36 C74 C114 C123 R18 R21 R22 R23 R25 R26 R34 R40 R42 R54 R55 R57 R58 R69 R73 R75 R83 R84 R90 R92 R95 R99 R104 R116 R119 R120 R121 R126 R127 R128 R129 R139 R140 R141 R142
